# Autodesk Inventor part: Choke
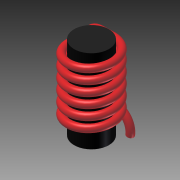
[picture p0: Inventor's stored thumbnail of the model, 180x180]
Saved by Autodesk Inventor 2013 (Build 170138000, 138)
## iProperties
Company: Autodesk Inc.
Created: 2005-12
Part Number: Choke
Document SubType Name: Modeling
Designer: Autodesk Inc.
Density: 1 g/cm^3
Mass: 0.341727 g
Surface Area: 6.53797 cm^2
Volume: 0.341727 cm^3
Material: Allgemein
Title: Personal Computer
Author: Autodesk Inc.
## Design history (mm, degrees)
sketch "Sketch1"
  geometry: L1 (0, 3.5)-(0, -3.5) reference; L2 (-3.5, 0)-(3.5, 0) reference; C1 r 2.5 at (0, 0)
  constraints: 2 midpoint, 1 centre point
  dimensions: "d0" = 5 diameter of C1
extrude "Extrusion1" new body sketch "Sketch1" distance "d1" = 12; taper "d2" = 0 deg
coil "Coil1" pitch "d6" = 1.5; turns "d8" = 5; dims "d7" = 10, "d9" = 0, angle "d10" = 180 deg, angle "d11" = 0 deg, "d12" = 180 deg, "d13" = 0
workaxis "Work Axis1"
workplane "Work Plane1"
sketch "Sketch4"
  geometry: L1 (-5.419, 0)-(5.745, 0) reference; L2 (0, -0.5)-(0, 0.5) reference; L3 (3.755, -2.055)-(3.755, -10.827); A1 r 30.157 centre (0, -30.157) between (1.879, -0.059) and (0, 0); A2 r 2 centre (1.755, -2.055) between (3.755, -2.055) and (1.879, -0.059)
  constraints: 4 point on circle, 3 tangent, 2 centre point, 2 end point, 1 midpoint, 1 parallel
  dimensions: "d15" = 2 radius of A2
sweep "Sweep1" sketch "Sketch4" dims "d16" = 0
sketch "Sketch6"
  geometry: L1 (0, -8.75)-(0, -7.75) reference; A1 r 2.395 centre (-0.117, -10.642) between (0, -8.25) and (-2.482, -11.02)
  constraints: 2 point on circle, 1 centre point
sweep "Sweep2" sketch "Sketch6" dims "d17" = 0
body "Solid1"
sketch "Sketch3"
  geometry: 4 further points
  constraints: 2 vertical alignment
sketch "Sketch2"
  geometry: L1 (0, 3.6)-(0, -0.6) reference; L2 (-2.5, 0)-(2.5, 0) reference; C1 r 0.5 at (3.1, 2.5); 1 further point
  constraints: 1 centre point
  dimensions: "d3" = 3.1 distance from line of L1 C1.centre; "d4" = 2.5 distance from line of L2 C1.centre; "d5" = 1 diameter of C1
node "Projected Loop1"
other parameters: "d14" = 0
